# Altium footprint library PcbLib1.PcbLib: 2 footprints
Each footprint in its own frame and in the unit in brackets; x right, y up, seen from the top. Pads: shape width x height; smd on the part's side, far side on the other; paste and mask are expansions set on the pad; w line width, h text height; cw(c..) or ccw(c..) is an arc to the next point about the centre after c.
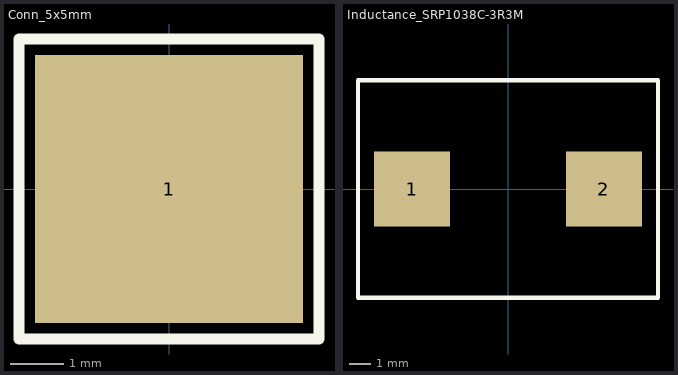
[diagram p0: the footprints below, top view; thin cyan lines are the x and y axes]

## Conn_5x5mm [mm]
pads (1):
  rect 5x5 smd: 1(0,0)
Top Overlay:
  lines w0.2: -2.794,-2.794 -2.794,2.794 2.794,2.794 2.794,-2.794 -2.794,-2.794

## Inductance_SRP1038C-3R3M [mm]
pads (2):
  rect 3.55x3.5 smd: 1(-4.475,0) 2(4.475,0)
Top Overlay:
  lines w0.2: -7,-5.08 7,-5.08 7,5.08 -7,5.08 -7,0 -7,-5.08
